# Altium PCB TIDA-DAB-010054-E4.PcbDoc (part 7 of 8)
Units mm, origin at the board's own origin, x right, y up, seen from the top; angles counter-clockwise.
Board outline 300 x 180 mm, 4 copper layers (Top Layer, Inner Layer1, Inner Layer2, Bottom Layer), stack 1.605 mm thick; 873 components, 388 nets, 2405 pads, 1542 vias.
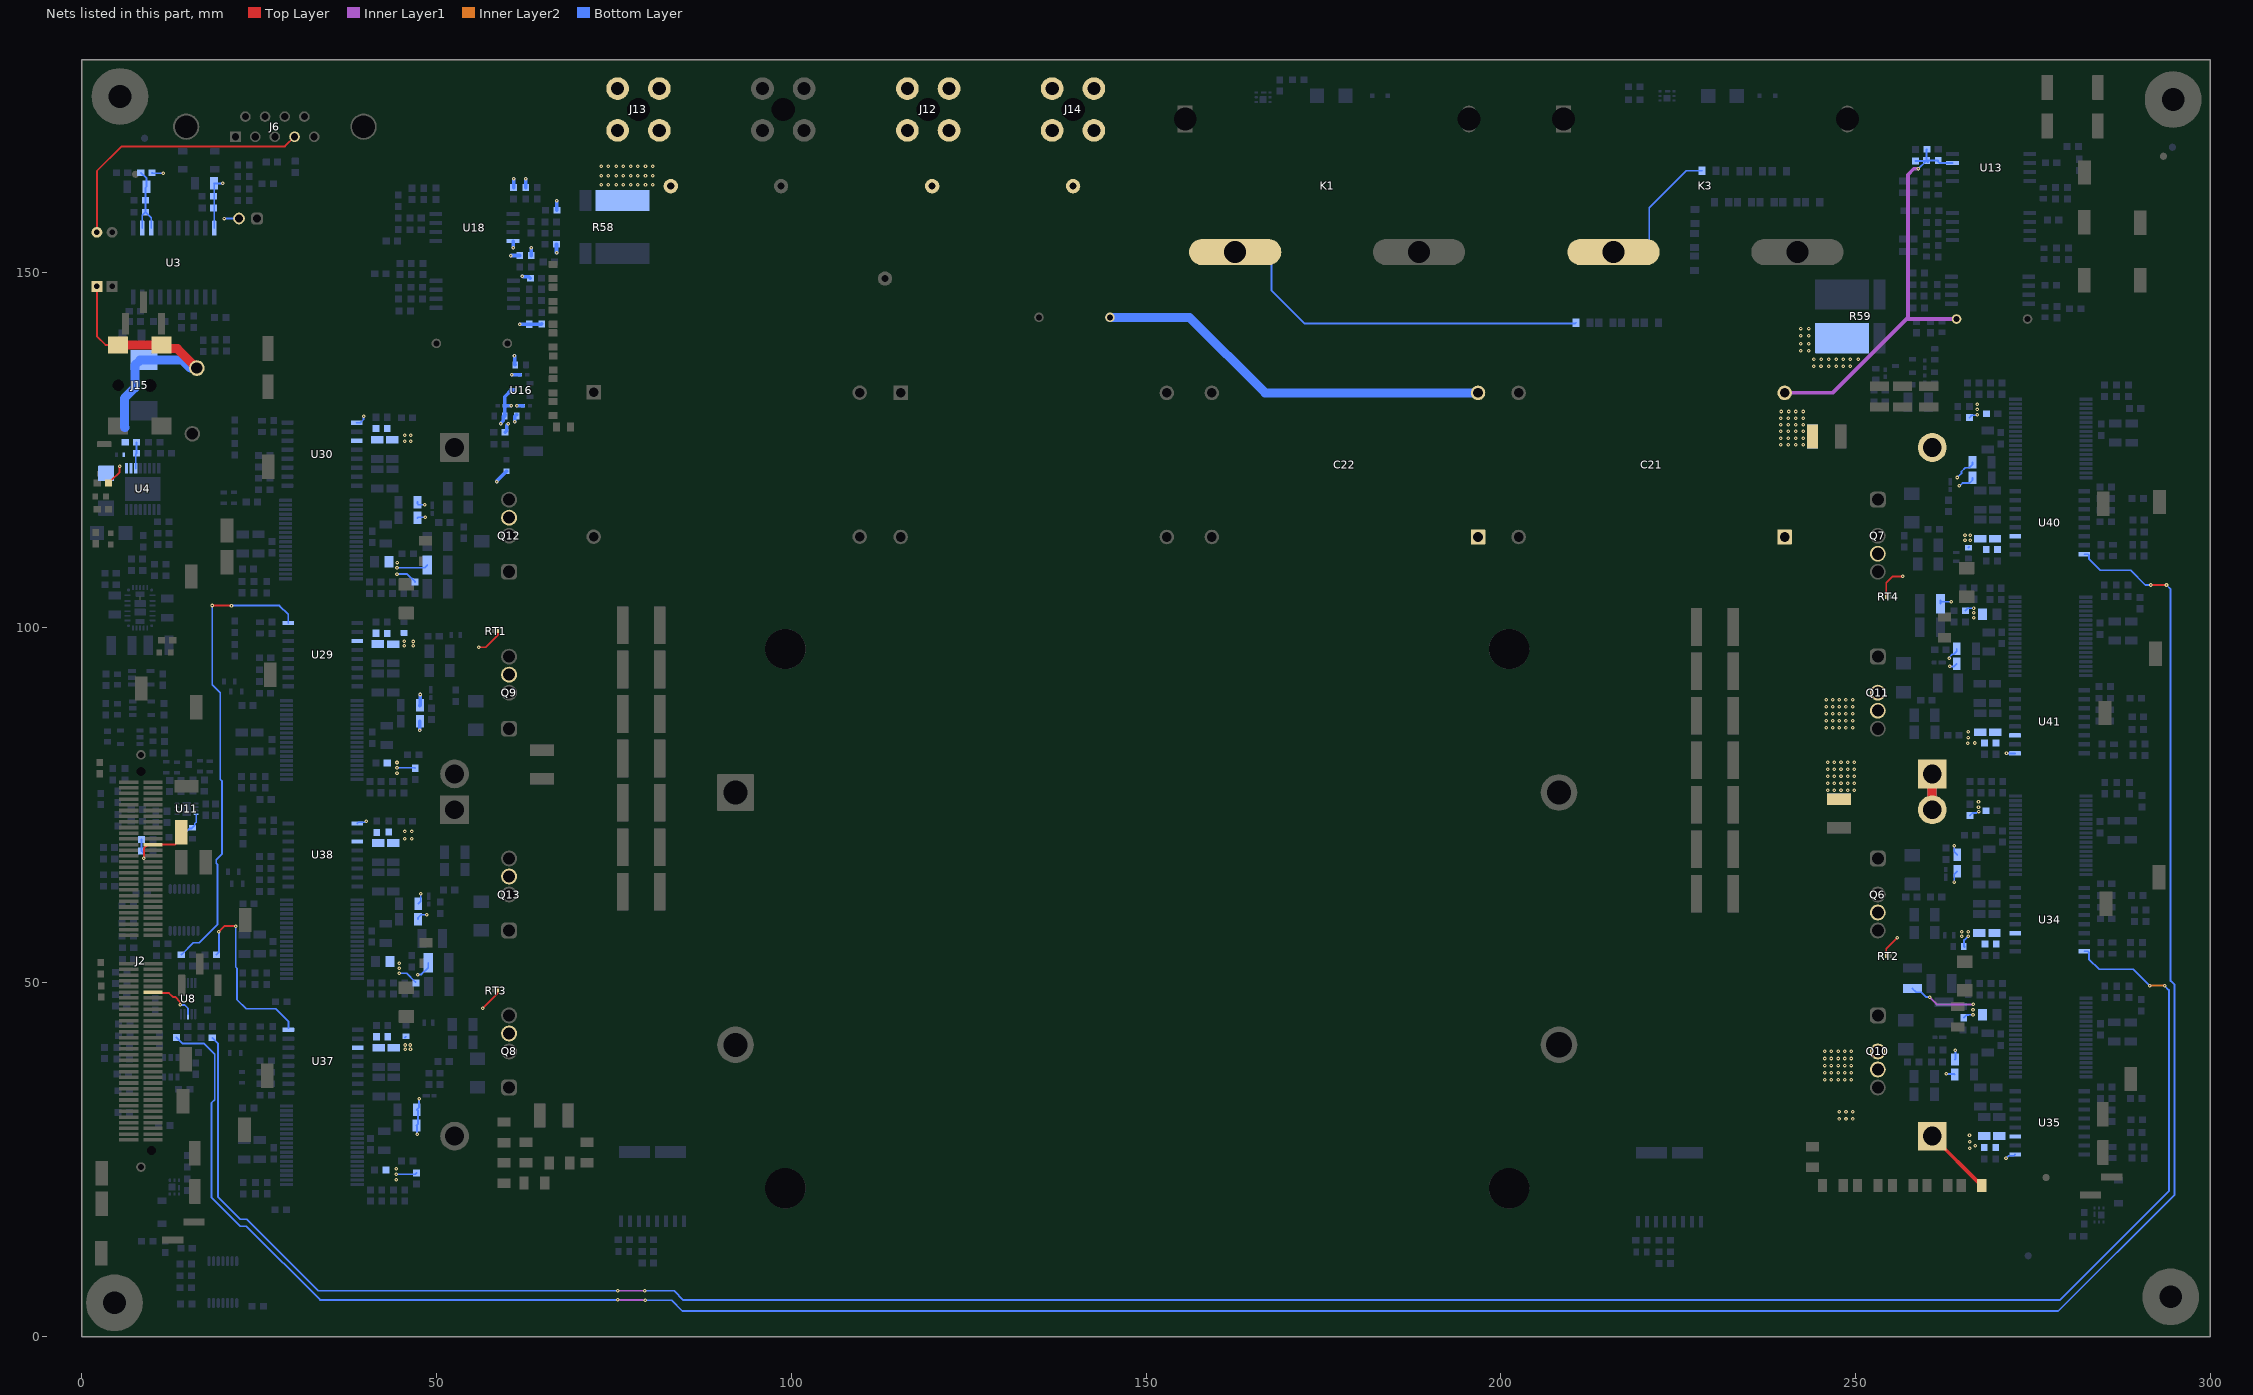
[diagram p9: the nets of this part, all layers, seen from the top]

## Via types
v1: diameter 0.5, hole 0.2, Top Layer to Bottom Layer, tented both sides, 1530 vias
v2: diameter 0.5, hole 0.2, Top Layer to Bottom Layer, 12 vias

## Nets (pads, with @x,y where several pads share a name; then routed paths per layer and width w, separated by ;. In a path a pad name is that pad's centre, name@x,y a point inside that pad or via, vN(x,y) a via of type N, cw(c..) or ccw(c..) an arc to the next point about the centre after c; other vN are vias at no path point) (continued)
S1H_P: C78.1 C169.2 C170.2 C178.1 C179.1 C188.2 Q9.3 R183.2 R189.2 R223.1 RT1.1 U29.3 | length 9.4
  Top Layer w0.254: v1(55.994,97.179) 56.966,97.179 58.675,98.887 RT1.1@58.675,99.457
  Bottom Layer w0.254: v1(44.456,80.188) 46.982,80.188 R189.2@47.039,80.131
  Bottom Layer w0.508: C170.2@47.673,86.762 47.678,86.758 v1(47.678,85.477) ; C169.2@47.683,88.981 47.75,89.047 v1(47.75,90.525)
  other v1: 44.456,79.435 44.456,80.94 45.472,97.411 46.738,97.401 45.453,98 46.738,97.995
S1H_S: C88.1 C196.2 C212.2 C220.1 C221.1 C230.2 Q6.3 R241.2 R247.2 R282.1 RT2.1 U34.3 | length 9.6
  Top Layer w0.254: RT2.1@254.305,53.668 254.305,54.715 v1(255.849,56.259)
  Bottom Layer w0.254: v1(263.891,64.096) 263.904,64.11 263.904,65.173 C212.2@264.327,65.596 ; v1(263.891,69.226) 263.904,69.213 263.904,68.347 C196.2@264.327,67.924 ; C88.1@265.35,54.951 265.283,55.018 265.283,55.917 v1(265.846,56.48) ; R247.2@266.119,73.455 266.119,73.48 266.467,73.828 267.021,73.828 267.225,74.032 v1(267.321,74.032)
  other v1: 264.966,56.452 264.966,57.083 265.851,57.083 267.311,74.641 267.311,75.393
S1L_P: C115.2 C116.1 C117.1 C118.2 C119.1 C120.2 C123.1 C127.2 C129.2 C130.2 C143.2 C144.2 C171.2 C172.2 C181.1 C182.1 C189.2 C272.2 C273.2 D12.2 Q12.3 R8.2 R36.2 R131.2 R171.1 R192.2 R224.1 U16.3 U18.4 U30.1 U30.3 | length 38.9
  Top Layer w0.254: v1(44.456,108.393) v1@44.552,108.393
  Bottom Layer w0.254: U30.1@38.765,128.831 39.29,128.831 39.735,129.276 39.735,129.683 v1(39.782,129.73) ; v1(44.456,107.485) 45.911,107.485 46.997,106.399 R192.2@46.997,106.374 ; v1(44.456,108.393) 48.351,108.393 R224.1@48.717,108.759 ; C172.2@47.348,115.406 47.438,115.497 v1(48.426,115.497) ; C171.2@47.348,117.639 47.348,117.402 47.474,117.276 v1(48.39,117.276)
  Bottom Layer w0.508: v1(58.496,120.498) 58.496,120.599 D12.2@59.891,121.994 ; v1(59.055,128.676) 59.055,128.704 59.445,129.094 59.445,129.729 59.666,129.95 C119.1@59.691,129.95 ; C119.1@59.658,129.769 C120.2@59.641,131.218 ; R131.2@59.691,127.467 59.716,127.467 59.937,127.688 59.937,128.492 v1(60.122,128.676) ; v1(60.505,152.345) 60.548,152.388 C144.2@61.768,152.388 ; v1(60.547,131.218) C120.2@59.641,131.218 ; v1(60.643,135.577) 60.645,135.575 61.791,135.575 C117.1@61.793,135.573 ; U16.3@60.797,133.426 60.597,133.426 59.641,132.47 C120.2@59.641,131.218 ; U18.4@60.81,154.415 60.84,154.385 v1(60.84,153.475) ; C130.2@60.886,161.94 v1(60.886,163.208) ; v1(61.006,138.243) 61.026,138.224 61.026,137.031 C118.2@61.074,136.982 ; v1(61.039,128.94) 61.058,128.959 61.058,129.729 61.279,129.95 C115.2@61.297,129.95 ; v1(61.36,131.218) 61.375,131.232 62.202,131.232 C116.1@62.206,131.236 ; v1(61.773,142.697) 63.081,142.697 63.104,142.673 64.783,142.673 C273.2@64.858,142.748 ; v1(62.131,149.474) 62.156,149.474 62.245,149.385 63.017,149.385 C272.2@63.238,149.164 ; C129.2@62.606,161.94 v1(62.606,163.19) ; v1(63.368,153.475) 63.368,152.408 C143.2@63.388,152.388 ; v1(66.936,152.8) C127.2@66.936,153.962 ; C123.1@66.975,158.767 66.979,158.772 66.979,160.095 v1(66.984,160.1)
  other v1: 44.478,109.12 45.524,126.236 46.411,126.236 45.524,127.05 46.411,127.05
S1L_S: C213.2 C214.2 C223.1 C224.1 C235.2 Q10.3 R9.2 R250.2 R284.1 R343.2 U35.1 U35.3 | length 15
  Inner Layer1 w0.254: v1(260.433,47.833) 261.406,46.86 v1(266.546,46.86)
  Bottom Layer w0.254: R343.2@258.005,49.099 258.528,48.576 259.228,48.576 259.925,47.88 260.386,47.88 v1(260.433,47.833) ; v1(262.775,37.052) 263.898,37.052 C213.2@263.97,36.98 ; C214.2@264.001,39.095 264.06,39.153 v1(264.06,40.415) ; R250.2@265.241,44.97 265.241,44.995 265.589,45.343 265.848,45.343 265.904,45.399 v1(266.535,45.399) ; v1(271.188,25.152) 271.57,25.535 272.302,25.535 U35.1@272.475,25.708
  other v1: 266.065,26.568 266.826,26.955 266.065,27.522 266.045,28.415 266.535,46.101
S2H_P: C94.1 C248.2 C249.2 C257.1 C258.1 C269.2 Q8.3 R288.2 R294.2 R325.1 RT3.1 U37.3 | length 11.8
  Top Layer w0.254: v1(56.508,46.324) 58.627,48.443 58.627,48.749 RT3.1@58.675,48.797
  Bottom Layer w0.254: v1(44.367,22.92) 47.016,22.92 R294.2@47.217,23.122 ; C94.1@45.593,42.189 C94.1@45.701,42.297 ; v1(47.289,28.54) 47.289,29.72 C249.2@47.216,29.793 47.4,29.977 47.4,31.949 47.289,31.949 C248.2@47.232,32.006 47.566,32.34 v1(47.566,33.543)
  other v1: 44.356,22.161 44.356,23.666 45.592,40.557 46.357,40.557 45.592,41.135 46.34,41.135
S2H_S: C95.1 C287.2 C288.2 C296.1 C297.1 C308.2 Q7.3 R328.2 R332.2 R377.1 RT4.1 U40.3 | length 12.1
  Top Layer w0.254: RT4.1@254.305,104.283 254.305,106.256 255.209,107.16 v1(256.651,107.16)
  Bottom Layer w0.254: v1(264.337,121.105) 264.919,121.687 264.919,121.949 265.454,122.484 266.027,122.484 266.45,122.907 C287.2@266.45,123.232 ; v1(264.603,119.927) 264.67,119.927 265.075,120.332 266.055,120.332 266.478,120.755 C288.2@266.478,121.08 ; C95.1@265.887,111.239 C95.1@265.986,111.338 ; R332.2@266.047,129.533 266.383,129.869 v1@267.291,129.869
  other v1: 265.41,112.268 266.128,112.268 265.41,112.957 266.135,112.957 267.147,129.941 267.15,130.689 267.15,131.446
S2L_P: C250.2 C251.2 C260.1 C261.1 C302.2 Q13.3 R11.2 R225.2 R290.2 R326.1 U38.1 U38.3 | length 10
  Bottom Layer w0.254: U38.1@38.866,72.357 39.039,72.53 39.891,72.53 40.052,72.69 v1(40.148,72.69) ; v1(44.744,51.243) 45.813,51.243 47.051,50.006 R290.2@47.051,49.981 ; v1(47.359,51.028) 47.406,51.075 47.896,51.075 48.847,52.026 R225.2@48.847,52.726 ; C251.2@47.416,58.877 47.416,59.055 47.839,59.478 v1(48.636,59.478) ; C250.2@47.444,61.025 47.806,61.387 v1(47.806,62.449)
  other v1: 44.762,51.96 44.759,52.65 45.565,70.175 46.544,70.175 45.565,71.223 46.544,71.223
S2L_S: C289.2 C290.2 C300.1 C301.1 C312.2 Q11.3 R12.2 R341.1 R347.2 R378.1 U41.1 U41.3 | length 7.6
  Bottom Layer w0.254: R341.1@261.95,103.304 261.95,103.76 262.104,103.605 v1(263.462,103.605) ; v1(263.183,95.643) 263.23,95.69 263.23,95.812 263.626,96.208 263.824,96.208 264.247,96.631 C289.2@264.247,96.956 ; v1(263.27,94.488) 263.87,94.488 C290.2@264.247,94.865 ; R347.2@265.467,102.34 265.793,102.667 v1(266.613,102.667) ; v1@271.167,82.231 271.174,82.224 v1(271.261,82.224) 271.265,82.228 272.451,82.228 U41.1@272.455,82.231
  other v1: 265.826,83.665 266.781,83.69 265.846,84.46 265.846,85.26 266.617,101.352 266.625,102.039
SGND: C15.2 C19.2 C21.1 C22.1 C25.2 C28.2 C59.1 C61.1 C105.2 C271.1 MP3.1 MP3.2 MP7.1 MP7.2 Q10.2 Q11.2 R22.1 R59.3 R115.1 R363.1 U13.3 | length 144.3
  Top Layer w0.508: MP3.1@260.799,28.28 267.734,21.345 R363.1@267.777,21.345
  Top Layer w1.27: MP3.2@260.791,74.28 MP7.1@260.791,78.839
  Inner Layer1 w0.508: C21.1@239.998,133.02 246.746,133.02 257.382,143.656 ; 257.433,143.437 257.382,143.488 257.382,143.656 ; 257.484,143.437 C61.1@264.222,143.437 ; v1(258.845,164.6) 258.199,164.6 257.382,163.783 257.382,143.656
  Inner Layer1 w1.27: MP3.2@260.791,74.28 MP7.1@260.791,78.839
  Inner Layer2 w1.27: MP3.2@260.791,74.28 MP7.1@260.791,78.839
  Bottom Layer w0.254: C271.1@258.427,165.706 R115.1@259.951,165.706 ; v1(258.845,164.6) R115.1@259.951,165.706 ; R22.1@260.042,167.356 259.976,167.29 R115.1@259.976,165.756 ; C105.2@261.573,165.687 261.845,165.415 U13.3@263.65,165.415 ; C105.2@261.642,165.756 R115.1@260.324,165.756 ; R115.1@259.951,165.706 259.976,165.731 R115.1@259.976,165.756 ; R115.1@259.976,165.756 260.191,165.541 260.191,165.623 R115.1@260.324,165.756 ; R115.1@259.976,165.756 R115.1@260.324,165.756
  Bottom Layer w1.27: C59.1@144.92,143.68 156.116,143.68 166.776,133.02 C22.1@196.789,133.02 ; MP3.2@260.791,74.28 MP7.1@260.791,78.839
  other v1: 247.705,30.709 248.64,30.709 249.58,30.709 247.705,31.704 248.64,31.704 249.58,31.704 245.652,36.247 246.588,36.247 247.523,36.247 248.459,36.247 249.399,36.247 245.652,37.243 246.588,37.243 247.523,37.243 248.459,37.243 249.399,37.243 245.652,38.238 246.588,38.238 247.523,38.238 248.459,38.238 249.399,38.238 245.652,39.233 246.588,39.233 247.523,39.233 248.459,39.233 249.399,39.233 245.652,40.229 246.588,40.229 247.523,40.229 248.459,40.229 249.399,40.229 246.062,77.007 246.998,77.007 247.934,77.007 248.869,77.007 249.809,77.007 246.062,78.002 246.998,78.002 247.934,78.002 248.869,78.002 249.809,78.002 246.062,78.998 246.998,78.998 247.934,78.998 248.869,78.998 249.809,78.998 246.062,79.993 246.998,79.993 247.934,79.993 248.869,79.993 249.809,79.993 246.062,80.988 246.998,80.988 247.934,80.988 248.869,80.988 249.809,80.988 245.83,85.819 246.766,85.819 247.701,85.819 248.637,85.819 249.577,85.819 245.83,86.815 246.766,86.815 247.701,86.815 248.637,86.815 249.577,86.815 245.83,87.81 246.766,87.81 247.701,87.81 248.637,87.81 249.577,87.81 245.83,88.806 246.766,88.806 247.701,88.806 248.637,88.806 249.577,88.806 245.83,89.801 246.766,89.801 247.701,89.801 248.637,89.801 249.577,89.801 239.464,125.72 240.509,125.72 241.554,125.72 242.599,125.72 239.464,126.66 240.509,126.66 241.554,126.66 242.599,126.66 239.464,127.596 240.509,127.596 241.554,127.596 242.599,127.596 239.464,128.531 240.509,128.531 241.554,128.531 242.599,128.531 239.464,129.467 240.509,129.467 241.554,129.467 242.599,129.467 239.523,130.402 240.548,130.402 241.574,130.402 242.599,130.402 244.119,136.791 245.119,136.791 246.219,136.791 247.239,136.791 248.251,136.791 249.251,136.791 244.128,137.739 245.128,137.739 246.228,137.739 247.248,137.739 248.26,137.739 249.26,137.739 250.36,137.739 242.248,138.974 243.38,138.974 242.248,139.974 243.38,139.974 242.248,141.074 243.38,141.074 242.248,142.094 243.38,142.094
TEMP_SENSE: J2.68 U8.8 | length 6.9
  Top Layer w0.254: J2.68@10.069,48.579 10.192,48.456 12.305,48.456 12.854,47.907 13.18,47.907 13.906,47.181 13.906,46.809 v1(13.916,46.799)
  Bottom Layer w0.254: v1(13.916,46.799) 13.942,46.772 14.547,46.772 15.006,46.313 15.006,45.5 U8.8@15.025,45.481
TMP_HB1_P: R86.2 U29.16 | length 65.2
  Top Layer w0.254: v1(18.427,103.064) 18.54,103.064 18.549,103.055 v1(21.13,103.055)
  Bottom Layer w0.254: R86.2@14.057,53.864 14.082,53.864 15.755,55.537 16.616,55.537 19.152,58.073 19.152,66.57 18.973,66.748 18.973,67.229 19.777,68.032 19.777,78.33 19.539,78.568 19.539,90.767 18.427,91.88 v1(18.427,103.064) ; v1(21.13,103.055) 27.879,103.055 29.116,101.818 U29.16@29.116,100.59
TMP_HB1_S: R30.2 U34.16 | length 353.2
  Inner Layer1 w0.254: v1(75.55,6.492) v1(79.385,6.492)
  Inner Layer2 w0.254: v1(291.428,49.483) 291.453,49.509 v1(293.56,49.509)
  Bottom Layer w0.254: R30.2@18.421,42.161 18.446,42.161 19.218,41.389 19.218,19.741 22.375,16.584 23.263,16.584 33.356,6.492 v1(75.55,6.492) ; v1(79.385,6.492) 83.494,6.492 84.798,5.188 278.783,5.188 294.14,20.545 294.14,48.862 293.56,49.442 v1(293.56,49.509) ; U34.16@282.225,54.355 282.699,54.355 282.872,54.182 282.872,53.242 284.317,51.797 289.114,51.797 v1(291.428,49.483)
TMP_HB2_P: R33.2 U37.16 | length 26
  Top Layer w0.254: v1(19.355,57.11) 20.131,57.887 v1(21.717,57.887)
  Bottom Layer w0.254: R33.2@19.014,53.864 19.355,54.205 v1(19.355,57.11) ; v1(21.717,57.887) 21.717,52.127 21.907,51.937 21.907,47.526 23.188,46.245 27.36,46.245 29.155,44.451 U37.16@29.155,43.485
TMP_HB2_S: R42.2 U40.16 | length 416.9
  Top Layer w0.254: v1(291.556,105.955) v1(293.805,105.954)
  Inner Layer1 w0.254: v1(75.539,5.213) 75.564,5.188 79.409,5.188 v1(79.434,5.163)
  Bottom Layer w0.254: R42.2@13.364,42.177 13.389,42.177 14.234,41.332 17.283,41.332 18.761,39.854 18.761,33.421 18.304,32.964 18.304,19.673 22.375,15.602 23.231,15.602 33.621,5.213 v1(75.539,5.213) ; v1(79.434,5.163) 83.148,5.163 84.663,3.649 278.56,3.649 294.947,20.036 294.947,49.604 294.38,50.171 294.38,105.383 293.808,105.954 v1(293.805,105.954) ; U40.16@282.225,110.291 282.718,110.291 282.891,110.118 282.891,109.61 284.465,108.037 288.747,108.037 290.829,105.955 v1(291.556,105.955)
UVLO_EFUSE: R69.1 R71.2 U4.3 | length 3.7
  Bottom Layer w0.254: U4.3@7.632,122.387 7.632,124.382 R71.2@7.757,124.507 7.756,124.508 7.756,126.081 R69.1@7.757,126.082
V_DC_PRI: C140.2 J2.24 R157.2 TP9.1 | length 10.8
  Top Layer w0.254: v1(8.791,67.457) 8.791,68.862 9.308,69.379 13.123,69.379 14.044,70.3 TP9.1@14.044,71.125
  Bottom Layer w0.254: R157.2@8.46,70.077 8.46,68.483 C140.2@8.464,68.479 ; C140.2@8.464,68.483 8.791,68.156 v1(8.791,67.457)
VBATT_N: J14.1 K3.3 R100.1 TP5.1 | length 19.9
  Bottom Layer w0.254: K3.3@215.89,152.87 219.311,152.87 220.903,154.462 220.903,159.13 226.109,164.336 R100.1@228.33,164.336
VBATT_P: J12.1 K1.3 R101.2 TP2.1 | length 54.5
  Bottom Layer w0.254: K1.3@162.57,152.87 166.073,152.87 167.665,151.278 167.665,147.475 172.321,142.819 210.501,142.819 R101.2@210.594,142.912
VBUS_N: J13.1 R58.1 TP4.1
  other v1: 73.24,162.33 74.24,162.33 75.34,162.33 76.36,162.33 77.372,162.33 78.372,162.33 79.472,162.33 80.492,162.33 73.24,163.64 74.24,163.64 75.34,163.64 76.36,163.64 77.372,163.64 78.372,163.64 79.472,163.64 80.492,163.64 73.24,164.95 74.24,164.95 75.34,164.95 76.36,164.95 77.372,164.95 78.372,164.95 79.472,164.95 80.492,164.95
VCC_OPA: C126.2 L15.2 U11.8 | length 4.3
  Bottom Layer w0.254: L15.2@13.969,70.4 15.196,71.627 15.477,71.627 15.963,72.112 15.963,72.373 15.988,72.373 16.155,72.54 U11.8@16.155,73.659
VIN_AUX: C62.1 D5.1 D7.2 J8.1 J15.1 J15.1A R68.2 R69.2 TP7.1 U4.1 U4.2 | length 45
  Top Layer w0.254: J8.1@2.164,148.03 2.164,140.996 3.374,139.786 J15.1@5.155,139.786 ; R68.2@3.816,120.316 3.841,120.316 4.189,120.664 4.189,120.689 5.36,121.86 v1(5.36,122.717)
  Top Layer w1.27: J15.1@5.155,139.786 J15.1A@11.455,139.786 ; J15.1A@11.255,139.786 11.763,139.279 13.502,139.279 TP7.1@16.256,136.525
  Bottom Layer w1.27: 6.124,128.129 6.033,128.22 6.033,132.262 7.506,133.735 7.506,136.892 D7.2@8.268,137.654 ; D7.2@8.776,137.654 D7.2@8.268,137.654 ; TP7.1@15.605,136.503 15.35,136.503 14.199,137.654 D7.2@8.268,137.654
VIN_AUX_CAN: J6.4 J8.2 | length 38.5
  Top Layer w0.254: J8.2@2.164,155.65 2.164,164.292 5.639,167.767 28.662,167.767 J6.4@30.015,169.12
VISOOUT: C12.1 C13.1 C14.1 L5.2 U3.12 U3.13 | length 11
  Bottom Layer w0.254: L5.2@8.342,164.029 8.69,163.681 8.784,163.681 9.142,163.324 C14.1@9.142,162.068 9.01,161.936 C13.1@9.01,160.162 9.01,158.483 C12.1@9,158.473 ; U3.12@8.545,156.24 8.545,158.043 8.975,158.473 C12.1@9,158.473 ; U3.13@9.815,156.24 9.815,157.684 9.025,158.473 C12.1@9,158.473
VP_CAN: C6.1 C7.1 C8.1 J10.2 L5.1 U3.20 | length 11.4
  Bottom Layer w0.254: L5.1@9.942,164.029 10.007,163.964 v1(11.533,163.964) ; C8.1@18.683,162.568 C8.1@18.705,162.546 ; U3.20@18.705,156.24 C8.1@18.705,162.546 ; v1(19.924,162.546) C8.1@18.705,162.546 ; v1@20.111,157.492 v1(20.111,157.596) J10.2@22.188,157.596
pads on no net: FID1.1 FID2.1 FID3.1 FID4.1 FID5.1 FID6.1 H1.1 H2.1 H3.1 H4.1 H5.0 H6.0 H7.0 H8.0 J2.1 J2.2 J2.3 J2.4 J2.5 J2.6 J2.8 J2.11 J2.12 J2.18 J2.20 J2.21 J2.26 J2.27 J2.28 J2.29 J2.30 J2.31 J2.32 J2.33 J2.34 J2.36 J2.37 J2.39 J2.40 J2.41 J2.42 J2.43 J2.44 J2.45 J2.66 J2.71 J2.73 J2.74 J2.75 J2.76 J2.77 J2.78 J2.85 J2.86 J2.87 J2.88 J2.89 J2.90 J2.91 J2.93 J2.95 J2.96 J2.104 J2.106 J2.107 J2.108 J2.109 J2.110 J2.113 J2.114 J2.115 J2.116 J2.117 J2.118 J2.119 J2.120 J2.181 J2.182 J2.185 J2.186 J6.1 J6.8 J11. J12. J13. J14. J15.MH1 J15.MH2 LBL1.0 MP13. MP14. MP15. MP16. MP17. MP18. MP19. MP20. RT1.1S RT1.2S RT2.1S RT2.2S RT3.1S RT3.2S RT4.1S RT4.2S T1. U2.4 U2.5 U3.2 U3.7 U3.14 U4.4 U4.13 U7.11 U7.20 U7.21 U7.26 U15.4 U15.5 U30.16 U35.16 U38.16 U41.16

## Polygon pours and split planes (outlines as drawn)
SGND on Inner Layer1 "INNER_LAYER1_SGND_P390" (solid, remove dead copper, pour order 390): 262.001,123.012 258.75,123.012 256.599,125.163 239.011,125.163 239.011,130.954 239.069,131.012 262.852,131.012 262.852,123.863
SGND on Inner Layer1 "INNER_LAYER1_SGND_P386" (solid, remove dead copper, pour order 386): 248.479,30.15 252.365,26.264 262.763,26.264 262.763,30.251 262.712,30.302 252.031,30.302 250.12,32.213 250.139,32.233 246.837,32.233 246.837,30.15
PGND on Inner Layer1 "INNER_LAYER1_PGND_P380" (solid, remove dead copper, pour order 380): 50.576,127.332 50.597,127.312 50.597,123.292 62.001,123.292 64.541,120.752 67.335,120.752 67.335,122.631 62.581,127.385
5V on Inner Layer1 "INNER_LAYER1_5V_P011" (solid, remove dead copper, pour order 11): 1.869,61.51 1.893,61.487 7.856,61.487 7.856,26.877 7.857,26.886 10.457,26.886 10.466,26.877 10.48,26.891 10.48,65.131 1.869,65.131
VBATT_N on Inner Layer1 "INNER_LAYER1_VBATT_N_P357" (solid, remove dead copper, pour order 357): 18 vertices, not listed, extent 133.16,149.24 223.44,177.6
3V3_A on Inner Layer1 "Inner Layer1-3V3_A" (solid, remove dead copper, pour order 351): 29 vertices, not listed, extent 1.615,65.615 50.7,163.9
3V3_D on Inner Layer1 "INNER_LAYER1_3V3_D_P330" (solid, remove dead copper, pour order 330): 36 vertices, not listed, extent 0.554,0.58 298.38,177.82
VP_CAN on Inner Layer1 "INNER_LAYER1_VP_CAN_P328" (solid, remove dead copper, pour order 328): 10.598,166.562 10.62,166.54 10.62,155.19 25.386,155.19 37.736,167.54 41.7,167.54 41.7,172.913 12.252,172.913 12.252,171.197 10.895,169.84 10.598,169.84
12V on Inner Layer1 "INNER_LAYER1_12V_P315" (solid, remove dead copper, pour order 315): 14.7,104.628 14.7,106.531 12.626,106.531 12.626,108.433 11.258,109.802 3.781,109.802 2.381,108.402 2.381,102.922 3.993,102.925 6.964,105.895 8.608,105.895 9.876,104.628
D1L_P on Inner Layer1 "INNER_LAYER1_D1L_P_P046" (solid, remove dead copper, pour order 46): 57.526,109.105 57.541,109.12 67.08,109.12 67.08,89.3 57.526,89.3 57.526,91.97 61.288,91.97 62.52,93.203 62.52,97.326 61.002,98.844 57.526,98.844
PGND on Inner Layer1 "INNER_LAYER1_PGND_P041" (solid, remove dead copper, pour order 41): 58.004,114.084 58.004,111.58 67.08,111.58 67.08,118.516 65.84,118.516 63.18,115.857 61.383,114.068
-4V_BOT3 on Inner Layer1 "INNER_LAYER1_-4V_BOT3_P308" (solid, remove dead copper, pour order 308): 273.43,34.262 267.622,34.262 267.622,50.532 273.43,50.532
-4V_TOP3 on Inner Layer1 "INNER_LAYER1_-4V_TOP3_P256" (solid, remove dead copper, pour order 256): 273.43,62.909 267.622,62.909 267.622,78.839 273.43,78.839
-4V_BOT4 on Inner Layer1 "INNER_LAYER1_-4V_BOT4_P247" (solid, remove dead copper, pour order 247): 273.43,91.115 267.622,91.115 267.622,106.88 273.43,106.88
-4V_TOP4 on Inner Layer1 "INNER_LAYER1_-4V_TOP4_P238" (solid, remove dead copper, pour order 238): 273.43,118.846 267.622,118.846 267.622,135.116 273.43,135.116
-4V_TOP2 on Inner Layer1 "INNER_LAYER1_-4V_TOP2_P229" (solid, remove dead copper, pour order 229): 37.95,34.759 43.758,34.759 43.758,18.596 37.95,18.596
-4V_BOT2 on Inner Layer1 "INNER_LAYER1_-4V_BOT2_P213" (solid, remove dead copper, pour order 213): 37.95,63.799 43.563,63.799 43.563,47.529 37.95,47.529
-4V_TOP1 on Inner Layer1 "INNER_LAYER1_-4V_TOP1_P040" (solid, remove dead copper, pour order 40): 38.05,92.033 43.695,92.033 43.695,75.763 38.05,75.763
-4V_BOT1 on Inner Layer1 "INNER_LAYER1_-4V_BOT1_P196" (solid, remove dead copper, pour order 196): 37.949,120.287 43.223,120.287 43.223,104.017 37.949,104.017
NetK3_4 on Inner Layer1 "INNER_LAYER1_NETK3_4_P188" (solid, remove dead copper, pour order 188): 233.88,144.737 233.88,155.229 233.86,155.249 251.884,155.104 251.884,144.737
SGND on Inner Layer1 "INNER_LAYER1_SGND_P171" (solid, remove dead copper, pour order 171): 244.77,84.074 244.77,89.865 247.205,92.3 255.394,92.3 255.394,89.654 255.3,89.56 250.639,89.56 250.639,84.493 250.22,84.074
D1L_S on Inner Layer1 "INNER_LAYER1_D1L_S_P162" (solid, remove dead copper, pour order 162): 255.371,54.275 252.248,54.275 251.18,55.343 251.18,60.7 251.64,61.16 254.4,61.16 254.4,63.92 246.89,63.92 244.77,61.8 244.77,44.04 255.371,44.04
D1H_S on Inner Layer1 "GND/PWR Layer1-D1H_S" (solid, remove dead copper, pour order 120): 53 vertices, not listed, extent 157.56,25.468 255.062,154.68
SGND on Inner Layer1 "INNER_LAYER1_SGND_P154" (solid, remove dead copper, pour order 154): 254.64,39.014 254.64,41.903 246.203,41.903 245.101,40.801 245.101,35.554 245.041,35.494 250.12,35.494 250.12,39.014
PGND on Inner Layer1 "INNER_LAYER1_PGND_P058" (solid, remove dead copper, pour order 58): 67.916,65.34 63.63,65.34 63.63,63.574 57.976,63.6 57.976,60.78 67.916,60.78
D2L_P on Inner Layer1 "INNER_LAYER1_D2L_P_P071" (solid, remove dead copper, pour order 71): 57.676,58.612 66.173,58.612 67.23,57.555 67.23,41.486 64.445,38.701 57.762,38.701 57.762,41.425 61.256,41.425 62.67,42.84 62.67,47.433 61.818,48.285 57.676,48.285
D2L_S on Inner Layer1 "INNER_LAYER1_D2L_S_P147" (solid, remove dead copper, pour order 147): 246.741,114.452 254.623,114.452 254.623,111.682 251.853,111.682 251.343,111.172 251.343,105.805 252.314,104.834 255.414,104.834 255.414,94.64 244.763,94.64 244.763,112.473
VBATT_P on Inner Layer1 "INNER_LAYER1_VBATT_P_P118" (solid, remove dead copper, pour order 118): 121.491,148.203 128.547,148.203 130.387,146.363 169.98,146.363 169.98,154.734 133.026,154.734 126.26,161.5 126.26,177.44 113.76,177.44 113.76,155.933
VBUS_N on Inner Layer1 "INNER_LAYER1_VBUS_N_P091" (solid, remove dead copper, pour order 91): 72.371,158.642 72.371,178.38 85.6,178.38 85.6,162.95 81.292,158.642
D1H_P on Inner Layer1 "INNER_LAYER1_D1H_P_P077" (solid, remove dead copper, pour order 77): 39 vertices, not listed, extent 57.76,31.394 154.551,177.599
SGND on Inner Layer2 "INNER_LAYER2_SGND_P389" (solid, remove dead copper, pour order 389): 262.001,123.012 258.75,123.012 256.599,125.163 239.011,125.163 239.011,130.954 239.069,131.012 262.852,131.012 262.852,123.863
SGND on Inner Layer2 "INNER_LAYER2_SGND_P383" (solid, remove dead copper, pour order 383): 248.479,30.15 252.365,26.264 262.763,26.264 262.763,30.251 262.712,30.302 252.031,30.302 250.12,32.213 250.139,32.233 246.837,32.233 246.837,30.15
GND_SEN_SEC on Inner Layer2 "INNER_LAYER2_GND_SEN_SEC_P360" (solid, remove dead copper, pour order 360): 252.4,136.4 264.46,136.4 264.46,167.83 256.94,167.83 252.4,163.29
VBATT_N on Inner Layer2 "INNER_LAYER2_VBATT_N_P278" (solid, remove dead copper, pour order 278): 18 vertices, not listed, extent 133.16,149.08 223.44,177.44
GND_ISO_CAN on Inner Layer2 "INNER_LAYER2_GND_ISO_CAN_P318" (solid, remove dead copper, pour order 318): 18 vertices, not listed, extent 0.58,154.62 41.7,172.913
GND_CAN on Inner Layer2 "INNER_LAYER2_GND_CAN_P003" (solid, remove dead copper, pour order 3): 5.64,147.751 5.64,145.868 5.596,145.868 3.42,143.692 3.42,139.786 21.696,139.786 21.766,139.856 21.766,147.694
GND on Inner Layer2 "INNER_LAYER2_GND_P063" (solid, remove dead copper, pour order 63): 41 vertices, not listed, extent 0.4,0.56 298.38,177.82
AGND on Inner Layer2 "INNER_LAYER2_AGND_P012" (solid, remove dead copper, pour order 12): 6.725,104.3 8.758,104.3 9.088,104.631 9.088,106.66 13.167,106.66 13.48,106.973 13.48,109.705 6.74,109.705 6.719,109.726
S2L_P on Inner Layer2 "INNER_LAYER2_S2L_P_P260" (solid, remove dead copper, pour order 260): 61.88,66.041 61.88,63.707 53.752,63.707 48.368,58.323 48.368,47.529 37.95,47.529 37.731,47.748 37.731,73.74 46.312,73.74 50.423,69.628 57.633,69.628 57.633,67.095 58.686,66.041
S2H_S on Inner Layer2 "INNER_LAYER2_S2H_S_P313" (solid, remove dead copper, pour order 313): 18 vertices, not listed, extent 251.884,106.66 273.325,132.081
S1L_P on Inner Layer2 "INNER_LAYER2_S1L_P_P216" (solid, remove dead copper, pour order 216): 19 vertices, not listed, extent 37.874,104.167 67.8,163.9
S2L_S on Inner Layer2 "INNER_LAYER2_S2L_S_P280" (solid, remove dead copper, pour order 280): 250.982,89.399 259.932,89.399 262.591,92.059 262.591,104.062 264.777,106.248 273.5,106.248 273.5,81.4 267.16,81.4 265.481,83.079 258.711,83.079 254.779,87.011 250.998,87.011
S1L_S on Inner Layer2 "INNER_LAYER2_S1L_S_P263" (solid, remove dead copper, pour order 263): 251.532,38.845 251.532,36.475 254.535,36.475 255.371,35.638 255.371,31.75 263.76,31.75 265.212,30.298 265.212,26.222 267.088,24.346 273.393,24.346 273.393,50.504 273.421,50.532 265.124,50.532 265.124,49.448 254.512,38.836
S1H_S on Inner Layer2 "INNER_LAYER2_S1H_S_P262" (solid, remove dead copper, pour order 262): 23 vertices, not listed, extent 251.88,52.993 273.476,76.089
SGND on Inner Layer2 "GND/PWR Layer2-SGND" (solid, remove dead copper, pour order 155): 47 vertices, not listed, extent 157.792,30.15 262.763,142.819
S2H_P on Inner Layer2 "INNER_LAYER2_S2H_P_P261" (solid, remove dead copper, pour order 261): 23 vertices, not listed, extent 37.904,21.589 61.697,46.82
D2L_P on Inner Layer2 "INNER_LAYER2_D2L_P_P093" (solid, remove dead copper, pour order 93): 57.676,58.612 66.173,58.612 67.23,57.555 67.23,41.486 64.445,38.701 57.762,38.701 57.762,41.368 61.198,41.368 62.67,42.84 62.67,47.415 61.8,48.285 57.676,48.285
S1H_P on Inner Layer2 "INNER_LAYER2_S1H_P_P042" (solid, remove dead copper, pour order 42): 21 vertices, not listed, extent 38.024,79.006 61.57,101.698
NetK3_4 on Inner Layer2 "INNER_LAYER2_NETK3_4_P206" (solid, remove dead copper, pour order 206): 233.88,144.737 233.88,155.229 233.86,155.249 251.884,155.104 251.884,144.737
D1H_S on Inner Layer2 "INNER_LAYER2_D1H_S_P189" (solid, remove dead copper, pour order 189): 254.665,66.125 254.665,69.805 251.801,72.669 244.82,72.669 244.82,66.125
D1L_S on Inner Layer2 "INNER_LAYER2_D1L_S_P170" (solid, remove dead copper, pour order 170): 255.371,54.275 252.248,54.275 251.18,55.343 251.18,60.7 251.64,61.16 254.4,61.16 254.4,63.92 246.89,63.92 244.77,61.8 244.77,44.04 255.371,44.04
PGND on Inner Layer2 "GND/PWR Layer2-PGND" (solid, remove dead copper, pour order 157): 52 vertices, not listed, extent 51.968,28.33 154.86,154.121
D1L_P on Inner Layer2 "INNER_LAYER2_D1L_P_P075" (solid, remove dead copper, pour order 75): 57.526,109.105 57.541,109.12 67.08,109.12 67.08,89.3 57.526,89.3 57.526,91.97 61.274,91.97 62.52,93.216 62.52,97.392 61.068,98.844 57.526,98.844
D1H_P on Inner Layer2 "INNER_LAYER2_D1H_P_P122" (solid, remove dead copper, pour order 122): 57.776,36.565 57.776,31.315 65.967,31.315 65.967,36.565
D1H_S on Inner Layer2 "INNER_LAYER2_D1H_S_P134" (solid, remove dead copper, pour order 134): 246.325,122.301 252.381,122.301 255.062,119.62 255.062,116.74 246.325,116.74
D2L_S on Inner Layer2 "INNER_LAYER2_D2L_S_P144" (solid, remove dead copper, pour order 144): 246.741,114.452 254.623,114.452 254.623,111.682 251.853,111.682 251.343,111.172 251.343,105.788 252.297,104.834 255.414,104.834 255.414,94.64 244.763,94.64 244.763,112.473
D1H_P on Inner Layer2 "INNER_LAYER2_D1H_P_P145" (solid, remove dead copper, pour order 145): 58.744,87.011 65.942,87.011 67.021,85.932 67.021,81.806 58.883,81.806 58.004,82.685 58.004,86.271
VBATT_P on Inner Layer2 "INNER_LAYER2_VBATT_P_P114" (solid, remove dead copper, pour order 114): 130.387,146.363 128.547,148.203 121.417,148.203 113.8,155.82 113.8,177.44 126.26,177.44 126.26,161.805 133.465,154.6 169.98,154.6 169.98,146.363
VBUS_N on Inner Layer2 "INNER_LAYER2_VBUS_N_P107" (solid, remove dead copper, pour order 107): 72.371,158.642 72.371,178.38 85.6,178.38 85.6,162.88 81.362,158.642
SGND on Bottom Layer "BOTTOM_LAYER_SGND_P387" (solid, remove dead copper, pour order 387): 248.479,30.15 252.365,26.264 262.763,26.264 262.763,30.251 262.712,30.302 252.031,30.302 250.12,32.213 250.139,32.233 246.837,32.233 246.837,30.15
SGND on Bottom Layer "BOTTOM_LAYER_SGND_P161" (solid, remove dead copper, pour order 161): 245.259,84.081 245.259,90.354 246.865,91.96 255.366,91.96 255.394,91.932 255.394,89.654 255.3,89.56 250.639,89.56 250.639,84.493 250.22,84.074
+15V_BOT3 on Bottom Layer "BOTTOM_LAYER_+15V_BOT3_P251" (solid, remove dead copper, pour order 251): 266.824,30.354 266.348,30.83 266.348,31.748 264.443,33.653 264.443,34.531 264.985,34.531 266.435,33.08 267.613,33.08 270.716,33.08 270.716,31.971 271.565,31.123 273.427,31.123 273.456,31.093 273.456,30.354 271.361,30.354
-4V_TOP3 on Bottom Layer "BOTTOM_LAYER_-4V_TOP3_P250" (solid, remove dead copper, pour order 250): 265.124,77.911 271.337,77.911 271.771,77.477 271.771,75.509 273.427,75.509 273.45,75.532 273.421,75.56 273.421,78.874 265.124,78.874
S2L_S on Bottom Layer "BOTTOM_LAYER_S2L_S_P234" (solid, remove dead copper, pour order 234): 273.325,85.12 271.997,85.12 271.477,85.64 265.341,85.64 265.341,83.079 270.252,83.079 271.586,84.412 273.325,84.412
GND_SEN_SEC on Bottom Layer "BOTTOM_LAYER_GND_SEN_SEC_P370" (solid, remove dead copper, pour order 370): 28 vertices, not listed, extent 252.19,132.671 261.642,138.228
PGND on Bottom Layer "Bottom Layer-PGND" (solid, remove dead copper, pour order 105): 22 vertices, not listed, extent 58.004,106.369 154.551,154.121
-4V_TOP2 on Bottom Layer "BOTTOM_LAYER_-4V_TOP2_P215" (solid, pour order 215): 46.256,19.757 40.043,19.757 39.609,20.191 39.609,22.159 37.953,22.159 37.93,22.137 37.959,22.108 37.959,18.596 46.256,18.596
12V on Bottom Layer "BOTTOM_LAYER_12V_P374" (solid, remove dead copper, pour order 374): 289.507,133.534 289.507,130.605 294.045,130.605 295.74,132.3 295.74,159.39 278.79,176.34 273.08,176.34 273.04,176.38 273.011,176.351 273.011,174.26 276.84,174.26 292.252,158.848 292.252,136.28
GND_ISO_CAN on Bottom Layer "BOTTOM_LAYER_GND_ISO_CAN_P314" (solid, remove dead copper, pour order 314): 25.032,164.797 27.715,164.797 28.934,163.578 28.934,161.699 27.641,160.407 25.032,160.407
-4V_SEN_SEC on Bottom Layer "BOTTOM_LAYER_-4V_SEN_SEC_P372" (solid, remove dead copper, pour order 372): 251.357,135.623 254.541,135.623 254.704,135.46 254.704,135.106 253.908,134.31 253.134,134.31 253.134,131.457 250.441,131.457 250.441,134.706
S1L_P on Bottom Layer "BOTTOM_LAYER_S1L_P_P179" (solid, remove dead copper, pour order 179): 44.923,107.118 44.294,107.118 42.883,108.529 42.489,108.529 42.489,109.595 44.923,109.595
5V_ISO_S on Bottom Layer "BOTTOM_LAYER_5V_ISO_S_P371" (solid, remove dead copper, pour order 371): 257.328,137.281 257.328,139.777 261.515,139.777 261.515,138.374 261.13,138.374 260.038,137.281
GND on Bottom Layer "BOTTOM_LAYER_GND_P368" (solid, remove dead copper, pour order 368): 223.019,175.389 223.019,176.635 225.78,176.635 225.76,176.615 225.76,175.389
RELAY_N on Bottom Layer "BOTTOM_LAYER_RELAY_N_P367" (solid, remove dead copper, pour order 367): 220.849,175.057 220.872,175.08 225.251,175.08 225.251,173.817 220.842,173.817
GND on Bottom Layer "BOTTOM_LAYER_GND_P366" (solid, remove dead copper, pour order 366): 283.788,16.902 283.788,19.375 281.588,19.375 281.588,16.902
NetD16_2 on Bottom Layer "BOTTOM_LAYER_NETD16_2_P365" (solid, pour order 365): 284.014,16.006 285.724,16.006 285.724,22.164 283.99,22.164
NetD13_2 on Bottom Layer "BOTTOM_LAYER_NETD13_2_P363" (solid, remove dead copper, pour order 363): 12.207,22.313 13.267,22.313 13.289,22.291 13.289,18.985 13.704,18.57 13.704,16.645 12.5,16.645 12.188,16.957 12.188,22.322
GND on Bottom Layer "BOTTOM_LAYER_GND_P362" (solid, remove dead copper, pour order 362): 13.586,21.359 13.586,19.155 15.475,19.155 15.466,19.164 15.466,21.359
VBATT_N on Bottom Layer "BOTTOM_LAYER_VBATT_N_P356" (solid, pour order 356): 160.648,161.637 163.9,164.89 163.9,164.952 188.385,164.952 191.7,161.637 223.44,161.637 223.44,149.08 208.52,149.08 200.06,157.54 138.16,157.54 133.16,162.54 133.16,177.44 145.22,177.44 145.22,167.52 151.103,161.637
GND on Bottom Layer "BOTTOM_LAYER_GND_P353" (solid, remove dead copper, pour order 353): 165.104,175.832 165.261,175.675 165.809,175.675 166.02,175.464 166.02,175.173 167.81,175.173 167.81,177.44 165.104,177.44
RELAY_P on Bottom Layer "BOTTOM_LAYER_RELAY_P_P352" (solid, remove dead copper, pour order 352): 165.21,174.904 165.21,173.91 167.71,173.91 167.81,173.81 167.81,174.904
GND on Bottom Layer "BOTTOM_LAYER_GND_P349" (solid, remove dead copper, pour order 349): 281.571,131.451 283.437,131.451 283.686,131.7 283.686,134.883 281.581,134.883 281.571,134.873
12V on Bottom Layer "BOTTOM_LAYER_12V_P348" (solid, remove dead copper, pour order 348): 281.577,128.065 289.8,128.065 289.8,130.263 285.997,130.263 284.91,129.176 281.577,129.176
GND on Bottom Layer "BOTTOM_LAYER_GND_P347" (solid, remove dead copper, pour order 347): 281.553,120.703 281.563,120.693 281.563,118.728 282.992,118.728 283.667,119.403 283.667,120.444 283.966,120.703 289.916,120.703 289.916,127.363 283.553,127.363 283.099,127.816 281.553,127.816
GND on Bottom Layer "BOTTOM_LAYER_GND_P345" (solid, remove dead copper, pour order 345): 281.551,103.391 283.417,103.391 283.666,103.64 283.666,106.823 281.561,106.823 281.551,106.813
12V on Bottom Layer "BOTTOM_LAYER_12V_P344" (solid, remove dead copper, pour order 344): 281.535,100.095 290.855,100.095 290.855,103.149 286.812,103.149 284.867,101.205 281.535,101.205
GND on Bottom Layer "BOTTOM_LAYER_GND_P343" (solid, remove dead copper, pour order 343): 281.533,92.643 281.543,92.633 281.543,90.668 282.972,90.668 283.647,91.343 283.647,92.384 283.946,92.643 289.738,92.643 289.738,99.303 283.533,99.303 282.894,99.942 281.533,99.942
GND on Bottom Layer "BOTTOM_LAYER_GND_P341" (solid, remove dead copper, pour order 341): 281.571,75.515 283.437,75.515 283.686,75.763 283.686,78.946 281.581,78.946 281.571,78.936
12V on Bottom Layer "BOTTOM_LAYER_12V_P340" (solid, remove dead copper, pour order 340): 281.567,72.077 290.83,72.077 290.83,74.981 286.693,74.981 284.899,73.187 281.567,73.187
GND on Bottom Layer "BOTTOM_LAYER_GND_P339" (solid, remove dead copper, pour order 339): 281.553,64.766 281.563,64.757 281.563,62.791 282.992,62.791 283.667,63.467 283.667,64.508 283.966,64.766 289.611,64.766 289.611,71.427 283.553,71.427 283.083,71.897 281.553,71.897
GND on Bottom Layer "BOTTOM_LAYER_GND_P333" (solid, remove dead copper, pour order 333): 281.571,46.867 283.437,46.867 283.686,47.116 283.686,50.299 281.581,50.299 281.571,50.289
12V on Bottom Layer "BOTTOM_LAYER_12V_P332" (solid, remove dead copper, pour order 332): 281.571,43.632 290.906,43.632 290.906,46.406 286.627,46.406 284.904,44.683 281.571,44.683
GND on Bottom Layer "BOTTOM_LAYER_GND_P331" (solid, remove dead copper, pour order 331): 281.571,36.243 281.581,36.233 281.581,34.268 283.01,34.268 283.686,34.943 283.686,35.984 283.984,36.243 286.255,36.243 289.738,39.726 289.738,42.903 284.006,42.903 283.536,43.374 281.571,43.374
NetC31_1 on Bottom Layer "BOTTOM_LAYER_NETC31_1_P127" (solid, remove dead copper, pour order 127): 17 vertices, not listed, extent 80.68,60.09 97.02,103.02
5V on Bottom Layer "BOTTOM_LAYER_5V_P320" (solid, remove dead copper, pour order 320): 1.343,92.224 7.864,92.224 7.866,92.222 7.866,91.083 1.343,91.083
GND_ISO_CAN on Bottom Layer "BOTTOM_LAYER_GND_ISO_CAN_P317" (solid, remove dead copper, pour order 317): 15.166,155.19 12.091,155.19 12.091,157.275 12.154,157.339 12.154,163.843 16.264,163.843 17.796,162.311 17.796,158.704 17.805,158.695 17.471,158.36 15.701,158.36 15.166,157.825
3V3_D on Bottom Layer "BOTTOM_LAYER_3V3_D_P324" (solid, remove dead copper, pour order 324): 9.019,87.951 15.093,87.951 15.093,87.139 9.019,87.139
5V on Bottom Layer "BOTTOM_LAYER_5V_P323" (solid, remove dead copper, pour order 323): 1.385,87.931 7.982,87.931 7.984,87.929 7.984,86.889 1.385,86.889
GND on Bottom Layer "BOTTOM_LAYER_GND_P322" (solid, remove dead copper, pour order 322): 2.436,90.804 2.436,88.165 13.664,88.165 13.664,90.804
3V3_A on Bottom Layer "BOTTOM_LAYER_3V3_A_P321" (solid, remove dead copper, pour order 321): 8.901,92.243 14.987,92.243 14.987,91.083 8.901,91.083
GND on Bottom Layer "BOTTOM_LAYER_GND_P319" (solid, remove dead copper, pour order 319): 2.318,94.913 2.318,92.633 13.546,92.633 13.546,94.913
GND on Bottom Layer "BOTTOM_LAYER_GND_P306" (solid, remove dead copper, pour order 306): 21 vertices, not listed, extent 2.082,95.111 13.115,103.77
12V on Bottom Layer "BOTTOM_LAYER_12V_P307" (solid, remove dead copper, pour order 307): 6.356,103.842 6.876,103.842 6.876,102.925 6.872,102.921 2.066,102.921 2.066,105.099 2.09,105.122 5.642,105.122 5.642,104.556
5V on Bottom Layer "BOTTOM_LAYER_5V_P309" (solid, remove dead copper, pour order 309): 10.681,101.219 10.815,101.084 10.815,94.995 5.875,94.995 5.875,100.944 6.149,101.219
12V on Bottom Layer "BOTTOM_LAYER_12V_P310" (solid, remove dead copper, pour order 310): 14.589,106.369 14.589,103.48 10.85,103.48 10.523,103.153 10.523,102.856 10.513,102.865 9.626,102.865 9.626,104.647 9.733,104.755 10.698,104.755 10.947,105.004 10.947,106.369
12V on Bottom Layer "BOTTOM_LAYER_12V_P305" (solid, remove dead copper, pour order 305): 5.128,115.661 5.084,115.704 2.318,115.704 2.318,117.987 5.307,117.987 6.057,117.237 7.352,117.237 7.352,110.916 6.172,109.736 6.172,108.722 3.012,108.722 3.012,109.816 5.128,111.932
RTN on Bottom Layer "BOTTOM_LAYER_RTN_P303" (solid, remove dead copper, pour order 303): 7.134,121.204 10.612,121.204 10.612,126.807 14.116,126.807 14.116,110.124 11.767,110.124 11.767,117.77 7.134,117.77
VIN_AUX on Bottom Layer "BOTTOM_LAYER_VIN_AUX_P302" (solid, remove dead copper, pour order 302): 5.581,123.548 5.581,129.27 5.848,129.27 6.886,128.233 6.886,123.423 7.161,123.148 7.161,121.747 5.932,121.747 4.908,120.723 2.256,120.723 2.256,122.934 4.967,122.934
GND on Bottom Layer "BOTTOM_LAYER_GND_P297" (solid, remove dead copper, pour order 297): 29.809,22.328 27.943,22.328 27.694,22.079 27.694,18.896 29.799,18.896 29.809,18.906
12V on Bottom Layer "BOTTOM_LAYER_12V_P296" (solid, remove dead copper, pour order 296): 29.809,25.563 21.936,25.563 21.936,23.425 26.143,23.425 27.23,24.512 29.809,24.512
GND on Bottom Layer "BOTTOM_LAYER_GND_P295" (solid, remove dead copper, pour order 295): 23.71,31.763 23.706,31.767 23.706,32.952 27.396,32.952 27.694,33.211 27.694,34.252 28.37,34.927 29.799,34.927 29.799,32.962 29.809,32.952 29.809,25.821 27.844,25.821 27.374,26.292 22.047,26.292 22.047,30.1
GND on Bottom Layer "BOTTOM_LAYER_GND_P293" (solid, remove dead copper, pour order 293): 29.809,51.368 27.943,51.368 27.694,51.119 27.694,47.936 29.799,47.936 29.809,47.946
12V on Bottom Layer "BOTTOM_LAYER_12V_P292" (solid, remove dead copper, pour order 292): 29.809,54.603 21.968,54.603 21.968,52.4 25.324,52.4 26.476,53.552 29.809,53.552
GND on Bottom Layer "BOTTOM_LAYER_GND_P291" (solid, remove dead copper, pour order 291): 23.706,59.041 21.987,57.321 21.987,55.321 22.1,55.208 27.497,55.208 27.844,54.861 29.809,54.861 29.809,61.992 29.799,62.002 29.799,63.967 28.37,63.967 27.694,63.292 27.694,62.251 27.396,61.992 23.706,61.992
GND on Bottom Layer "BOTTOM_LAYER_GND_P285" (solid, remove dead copper, pour order 285): 29.769,79.433 27.903,79.433 27.655,79.185 27.655,76.002 29.76,76.002 29.769,76.012
12V on Bottom Layer "BOTTOM_LAYER_12V_P284" (solid, remove dead copper, pour order 284): 21.615,81.476 21.615,83.083 23.876,83.083 27.33,83.083 27.33,83.05 27.711,82.669 29.769,82.669 29.769,81.618 27.414,81.618 26.327,80.531 21.615,80.531
GND on Bottom Layer "BOTTOM_LAYER_GND_P283" (solid, remove dead copper, pour order 283): 23.899,83.652 21.806,83.652 21.806,86.652 23.667,88.519 23.667,90.058 27.356,90.058 27.655,90.317 27.655,91.357 28.33,92.033 29.76,92.033 29.76,90.067 29.769,90.058 29.769,82.927 27.805,82.927 27.08,83.652
-4V_BOT4 on Bottom Layer "BOTTOM_LAYER_-4V_BOT4_P241" (solid, remove dead copper, pour order 241): 264.655,104.947 271.771,104.947 271.771,103.714 273.427,103.714 273.45,103.737 273.421,103.765 273.421,106.001 264.655,106.001
D2L_S on Bottom Layer "BOTTOM_LAYER_D2L_S_P123" (solid, remove dead copper, pour order 123): 19 vertices, not listed, extent 232.06,59.8 255.394,113.989
NetC32_2 on Bottom Layer "BOTTOM_LAYER_NETC32_2_P125" (solid, remove dead copper, pour order 125): 205.34,70.08 217.38,70.08 219.44,68.02 219.44,61.7 221.48,59.66 228.34,59.66 228.3,102.66 221.4,102.66 219.44,100.7 219.44,87.06 216.991,84.611 205.63,84.611 203.9,82.881 203.9,71.52
GND on Bottom Layer "BOTTOM_LAYER_GND_P267" (solid, remove dead copper, pour order 267): 29.669,107.688 27.803,107.688 27.554,107.439 27.554,104.256 29.659,104.256 29.669,104.266
12V on Bottom Layer "BOTTOM_LAYER_12V_P266" (solid, remove dead copper, pour order 266): 29.669,110.923 21.733,110.923 21.733,108.785 25.956,108.785 27.043,109.872 29.669,109.872
GND on Bottom Layer "BOTTOM_LAYER_GND_P265" (solid, remove dead copper, pour order 265): 25.313,111.738 21.808,111.738 21.808,114.797 23.952,116.948 23.952,118.312 27.256,118.312 27.554,118.571 27.554,119.612 28.23,120.287 29.659,120.287 29.659,118.322 29.669,118.312 29.669,111.181 27.704,111.181 27.147,111.738
-4V_BOT4 on Bottom Layer "BOTTOM_LAYER_-4V_BOT4_P235" (solid, remove dead copper, pour order 235): 271.041,91.31 271.52,90.83 273.382,90.83 273.382,98.9 271.846,98.9 271.831,98.915 271.435,98.519 268.424,98.519 267.76,97.856 266.008,97.856 266.008,91.31
-4V_BOT3 on Bottom Layer "BOTTOM_LAYER_-4V_BOT3_P259" (solid, remove dead copper, pour order 259): 265.124,49.264 271.337,49.264 271.771,48.83 271.771,46.862 273.427,46.862 273.45,46.884 273.421,46.913 273.421,50.403 265.124,50.403
S1L_S on Bottom Layer "BOTTOM_LAYER_S1L_S_P258" (solid, remove dead copper, pour order 258): 266.225,47.432 267.111,47.432 268.522,46.021 268.522,44.57 266.225,44.57
-4V_BOT3 on Bottom Layer "BOTTOM_LAYER_-4V_BOT3_P255" (solid, remove dead copper, pour order 255): 268.651,44.341 268.983,44.341 271.247,44.341 271.602,44.677 273.476,44.677 273.476,43.626 273.447,43.597 268.651,43.597
+15V_BOT3 on Bottom Layer "BOTTOM_LAYER_+15V_BOT3_P254" (solid, remove dead copper, pour order 254): 264.493,42.583 267.414,42.583 267.414,43.188 267.613,43.397 273.476,43.397 273.476,42.308 273.46,42.292 271.635,42.279 271.22,41.864 268.257,41.864 266.91,40.517 264.483,40.517 264.483,42.572
-4V_BOT3 on Bottom Layer "BOTTOM_LAYER_-4V_BOT3_P253" (solid, remove dead copper, pour order 253): 273.456,34.262 271.092,34.262 266.008,34.262 266.008,40.145 266.902,40.145 268.424,41.667 271.435,41.667 271.831,42.062 271.846,42.047 273.456,42.047
S1L_S on Bottom Layer "BOTTOM_LAYER_S1L_S_P252" (solid, remove dead copper, pour order 252): 265.241,26.226 265.212,26.255 264.996,26.255 264.996,28.788 273.442,28.788 273.442,28.079 273.456,28.065 273.456,27.804 271.831,27.804 270.252,26.226
S1H_S on Bottom Layer "BOTTOM_LAYER_S1H_S_P249" (solid, remove dead copper, pour order 249): 266.844,75.945 267.246,75.945 268.46,74.73 268.916,74.73 268.916,73.602 266.844,73.602
-4V_TOP3 on Bottom Layer "BOTTOM_LAYER_-4V_TOP3_P246" (solid, remove dead copper, pour order 246): 273.476,73.325 268.674,73.325 268.674,72.245 273.447,72.245 273.476,72.273
+15V_TOP3 on Bottom Layer "BOTTOM_LAYER_+15V_TOP3_P245" (solid, remove dead copper, pour order 245): 273.46,70.94 273.476,70.956 273.476,72.044 267.069,72.044 264.668,69.644 264.668,69.245 267.067,69.245 268.334,70.512 271.22,70.512 271.635,70.927
-4V_TOP3 on Bottom Layer "BOTTOM_LAYER_-4V_TOP3_P244" (solid, remove dead copper, pour order 244): 273.456,62.909 271.092,62.909 266.008,62.909 266.008,68.792 266.902,68.792 268.424,70.314 271.435,70.314 271.831,70.71 271.846,70.695 273.456,70.695
S1H_S on Bottom Layer "BOTTOM_LAYER_S1H_S_P243" (solid, remove dead copper, pour order 243): 267.747,54.874 267.602,55.018 264.566,55.018 264.566,57.435 273.442,57.435 273.442,56.727 273.456,56.712 273.456,56.452 271.831,56.452 270.252,54.874
+15V_TOP3 on Bottom Layer "BOTTOM_LAYER_+15V_TOP3_P242" (solid, remove dead copper, pour order 242): 273.456,59.08 273.456,59.741 273.427,59.77 271.565,59.77 270.538,60.797 270.538,61.728 264.371,61.728 264.371,59.002 271.361,59.002 271.44,59.08 271.831,59.08
S2L_S on Bottom Layer "BOTTOM_LAYER_S2L_S_P240" (solid, remove dead copper, pour order 240): 267.484,100.985 266.217,100.985 266.217,103.2 267.594,103.2 268.262,102.532 268.524,102.532 268.524,100.985
-4V_BOT4 on Bottom Layer "BOTTOM_LAYER_-4V_BOT4_P237" (solid, remove dead copper, pour order 237): 271.502,101.256 271.037,100.791 268.105,100.791 268.105,100.04 273.329,100.04 273.493,100.205 273.493,101.256
+15V_BOT4 on Bottom Layer "BOTTOM_LAYER_+15V_BOT4_P236" (solid, remove dead copper, pour order 236): 264.315,99.874 264.315,98.177 267.008,98.177 267.817,98.987 271.49,98.987 271.635,99.132 273.46,99.145 273.476,99.161 273.476,99.874
+15V_BOT4 on Bottom Layer "BOTTOM_LAYER_+15V_BOT4_P233" (solid, remove dead copper, pour order 233): 273.325,86.932 273.325,87.719 271.821,87.719 270.855,88.685 270.855,89.933 264.371,89.933 264.371,86.932 271.086,86.932
-4V_TOP4 on Bottom Layer "BOTTOM_LAYER_-4V_TOP4_P232" (solid, remove dead copper, pour order 232): 265.124,133.848 271.337,133.848 271.771,133.414 271.771,131.446 273.427,131.446 273.45,131.468 273.421,131.497 273.421,134.112 272.417,135.116 265.124,135.116
S2H_S on Bottom Layer "BOTTOM_LAYER_S2H_S_P231" (solid, remove dead copper, pour order 231): 266.774,132.016 267.111,132.016 268.522,130.605 268.916,130.605 268.916,129.539 266.774,129.539
-4V_TOP4 on Bottom Layer "BOTTOM_LAYER_-4V_TOP4_P228" (solid, remove dead copper, pour order 228): 271.599,128.181 271.28,128.5 268.651,128.5 268.651,129.261 273.476,129.261 273.476,128.21 273.447,128.181
+15V_TOP4 on Bottom Layer "BOTTOM_LAYER_+15V_TOP4_P227" (solid, remove dead copper, pour order 227): 273.445,126.745 273.445,127.808 273.431,127.822 271.494,127.822 271.033,128.293 265.38,128.293 265.38,126.391 265.778,125.992 267.092,125.992 267.844,126.745
-4V_TOP4 on Bottom Layer "BOTTOM_LAYER_-4V_TOP4_P226" (solid, remove dead copper, pour order 226): 267.534,125.362 267.534,118.846 273.456,118.846 273.456,126.631 271.846,126.631 271.831,126.646 271.435,126.251 268.424,126.251
S2H_S on Bottom Layer "BOTTOM_LAYER_S2H_S_P225" (solid, remove dead copper, pour order 225): 271.366,111.461 271.366,112.147 271.607,112.388 273.456,112.388 273.456,112.648 273.442,112.663 273.442,113.372 265.319,113.372 265.012,113.065 265.012,111.039 265.572,110.48 270.385,110.48
+15V_TOP4 on Bottom Layer "BOTTOM_LAYER_+15V_TOP4_P224" (solid, remove dead copper, pour order 224): 273.456,115.016 273.456,115.677 273.427,115.707 271.565,115.707 270.855,116.417 270.855,117.124 264.915,117.124 264.915,114.632 271.055,114.632 271.44,115.016 271.831,115.016
NetK3_4 on Bottom Layer "BOTTOM_LAYER_NETK3_4_P172" (solid, remove dead copper, pour order 172): 235.28,144.737 235.28,154.902 251.884,154.902 251.884,144.737
SGND on Bottom Layer "BOTTOM_LAYER_SGND_P222" (solid, remove dead copper, pour order 222): 250.22,75.235 250.22,81.4 245.569,81.4 245.569,75.235
SGND on Bottom Layer "Bottom Layer-SGND" (solid, remove dead copper, pour order 221): 157.792,106.369 241.375,106.369 241.375,125.163 244.143,125.163 244.143,131.012 242.56,131.012 242.56,133.671 248.514,133.671 251.884,137.042 251.884,142.819 236.535,142.819 230.996,137.28 157.882,137.28 157.792,137.37
D1H_S on Bottom Layer "BOTTOM_LAYER_D1H_S_P218" (solid, remove dead copper, pour order 218): 246.325,123.58 247.1,124.355 247.1,128.522 251.102,128.522 251.102,123.58 254.505,120.177 254.505,117.124 246.325,117.124
S2H_P on Bottom Layer "BOTTOM_LAYER_S2H_P_P214" (solid, remove dead copper, pour order 214): 44.898,21.589 44.269,21.589 42.858,23 42.464,23 42.464,24.066 44.898,24.066
-4V_TOP2 on Bottom Layer "BOTTOM_LAYER_-4V_TOP2_P211" (solid, remove dead copper, pour order 211): 37.904,24.344 42.729,24.344 42.729,25.424 37.933,25.424 37.904,25.395
+15V_TOP2 on Bottom Layer "BOTTOM_LAYER_+15V_TOP2_P210" (solid, remove dead copper, pour order 210): 37.92,26.729 37.904,26.713 37.904,25.624 46.897,25.624 46.897,28.192 44.868,28.192 43.563,26.887 39.89,26.887 39.745,26.742
-4V_TOP2 on Bottom Layer "BOTTOM_LAYER_-4V_TOP2_P209" (solid, remove dead copper, pour order 209): 37.924,34.759 40.288,34.759 45.372,34.759 45.372,28.876 44.478,28.876 42.956,27.354 39.945,27.354 39.549,26.959 39.534,26.974 37.924,26.974
S2H_P on Bottom Layer "BOTTOM_LAYER_S2H_P_P208" (solid, remove dead copper, pour order 208): 46.139,42.795 46.168,42.766 47.25,42.766 47.25,40.237 47.254,40.233 37.938,40.233 37.938,40.942 37.924,40.957 37.924,41.217 39.549,41.217 41.128,42.795
+15V_TOP2 on Bottom Layer "BOTTOM_LAYER_+15V_TOP2_P207" (solid, remove dead copper, pour order 207): 37.924,38.589 37.924,37.928 37.953,37.898 39.815,37.898 40.525,37.188 40.525,35.941 47.009,35.941 47.009,38.667 40.019,38.667 39.94,38.589 39.549,38.589
S2L_P on Bottom Layer "BOTTOM_LAYER_S2L_P_P197" (solid, remove dead copper, pour order 197): 45.276,50.629 44.269,50.629 42.858,52.04 42.464,52.04 42.464,53.776 45.276,53.776
PGND on Bottom Layer "BOTTOM_LAYER_PGND_P202" (solid, remove dead copper, pour order 202): 68.44,28.33 68.44,33.127 72.417,33.127 72.417,28.33
PGND on Bottom Layer "BOTTOM_LAYER_PGND_P200" (solid, remove dead copper, pour order 200): 51.968,79.503 51.968,73.79 67.916,73.79 67.916,79.503
-4V_BOT2 on Bottom Layer "BOTTOM_LAYER_-4V_BOT2_P198" (solid, remove dead copper, pour order 198): 46.256,48.797 40.043,48.797 39.609,49.231 39.609,51.199 37.953,51.199 37.93,51.177 37.959,51.148 37.959,47.701 46.256,47.701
